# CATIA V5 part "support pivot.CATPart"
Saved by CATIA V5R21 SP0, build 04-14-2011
Part number: SupportPivot
Bounding box of the stored display mesh (mm): x -21 to 21, y -21 to 38, z 0 to 27
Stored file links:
  C:\Users\2027.DESARCY-LEMIE30\Desktop\V16(05.04.2023)\support pivot.CATPart
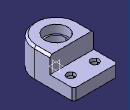
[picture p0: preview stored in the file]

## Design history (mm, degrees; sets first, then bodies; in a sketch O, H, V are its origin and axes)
Body1 (main body)
  Sketch1 on xy-plane, origin (0, 0, 0), H (1, 0, 0), V (0, 1, 0)
    arc A1 centre (0, 0) radius 21 from (-21, 0) to (21, 0) ccw
    line L1 (-21, 15) -> (21, 15)
    line L2 (21, 15) -> (21, 0)
    line L3 (-21, 0) -> (-21, 15)
    radius A1 = 21
    length L1 = 42
    distance L1 H = 15
    horizontal: L1 H
    vertical: L2 V, L3 V
  Pad1: profile Sketch1, direction (0, 0, 1), length 27
  Sketch2 on xy-plane, origin (0, 0, 0), H (1, 0, 0), V (0, 1, 0)
    line L1 (21, 0) -> (21, 38)
    line L2 (21, 38) -> (-21, 38)
    line L3 (-21, 38) -> (-21, 0)
    line L4 (-21, 0) -> (21, 0)
    distance L2 H = 38
    distance L1 V = 21
    length L2 = 42
    horizontal: L2 H, L4 H
    vertical: L1 V, L3 V
  Pad2: profile Sketch2, direction (0, 0, 1), length 11
  Sketch3 on end face of Pad1, origin (1.3571, -8.2844, 27), H (1, 0, 0), V (0, 1, 0)
    point P1 (-1.3571, 8.2844)
    reference projected arc E1 centre (-1.3571, 8.2844) radius 21 from (-22.3571, 8.2844) to (19.6429, 8.2844) ccw from edge [face of Pad1 from Sketch1.A1 | end face of Pad1]
    reference intersected line E2 through (-1.3571, 0) direction (0, 1) from yz-plane
    reference intersected line E3 through (0, 8.2844) direction (-1, 0) from zx-plane
    radius E1 = 21 (reference)
    distance P1 E2 = 0
    distance E3 P1 = 0
  Hole1: placed by Sketch3, at (0, 0, 27) direction (0, 0, -1), diameter 22, through (limit type 6)
  Sketch4 on face of Pad2, origin (-11.5216, 25.6596, 0), H (1, 0, 0), V (0, -1, 0)
    point P1 (0.0216, 0.1596)
    reference projected line E1 (-9.4784, 10.6596) -> (-9.4784, 25.6596) from edge [face of Pad2 | face of Pad2]
    reference projected line E2 (32.5216, -12.3404) -> (-9.4784, -12.3404) from edge [start face of Pad2 | face of Pad2 from Sketch2.L2]
    distance P1 E1 = 9.5
    distance P1 E2 = 12.5
  Hole2: placed by Sketch4, at (-11.5, 25.5, 0) direction (0, 0, 1), diameter 7.9, through (limit type 6), counterbore diameter 12.76, counterbore depth 8
  Sketch5 on face of Pad2, origin (12.0454, 25.2497, 0), H (1, 0, 0), V (0, -1, 0)
    point P1 (-0.5454, -0.2503)
    reference projected line E1 (8.9546, 25.2497) -> (8.9546, 10.2497) from edge [face of Pad2 | face of Pad2]
    reference projected line E2 (8.9546, -12.7503) -> (-33.0454, -12.7503) from edge [start face of Pad2 | face of Pad2 from Sketch2.L2]
    distance P1 E1 = 9.5
    distance P1 E2 = 12.5
  Hole3: placed by Sketch5, at (11.5, 25.5, 0) direction (0, 0, 1), diameter 7.9, through (limit type 6), counterbore diameter 12.76, counterbore depth 8
  Chamfer1: length 2, angle 45, on edge [face of Pad2 from Sketch2.L2 | face of Pad2]
  Chamfer2: length 2, angle 45, on edge [face of Pad1 from Sketch1.A1 | end face of Pad1]
  Chamfer3: length 2, angle 45, on edge [face of Pad2 | face of Pad2 from Sketch2.L2]
  Sketch6 on xy-plane, origin (0, 0, 0), H (1, 0, 0), V (0, 1, 0)
    circle A1 centre (0, 0) radius 9.5
    projected circle E1 centre (0, 0) radius 11 from edge [end face of Pad1 | face of Hole1]
    radius A1 = 9.5
  Pad3: profile Sketch6, direction (0, 0, 1), length 19, opposite side length -7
